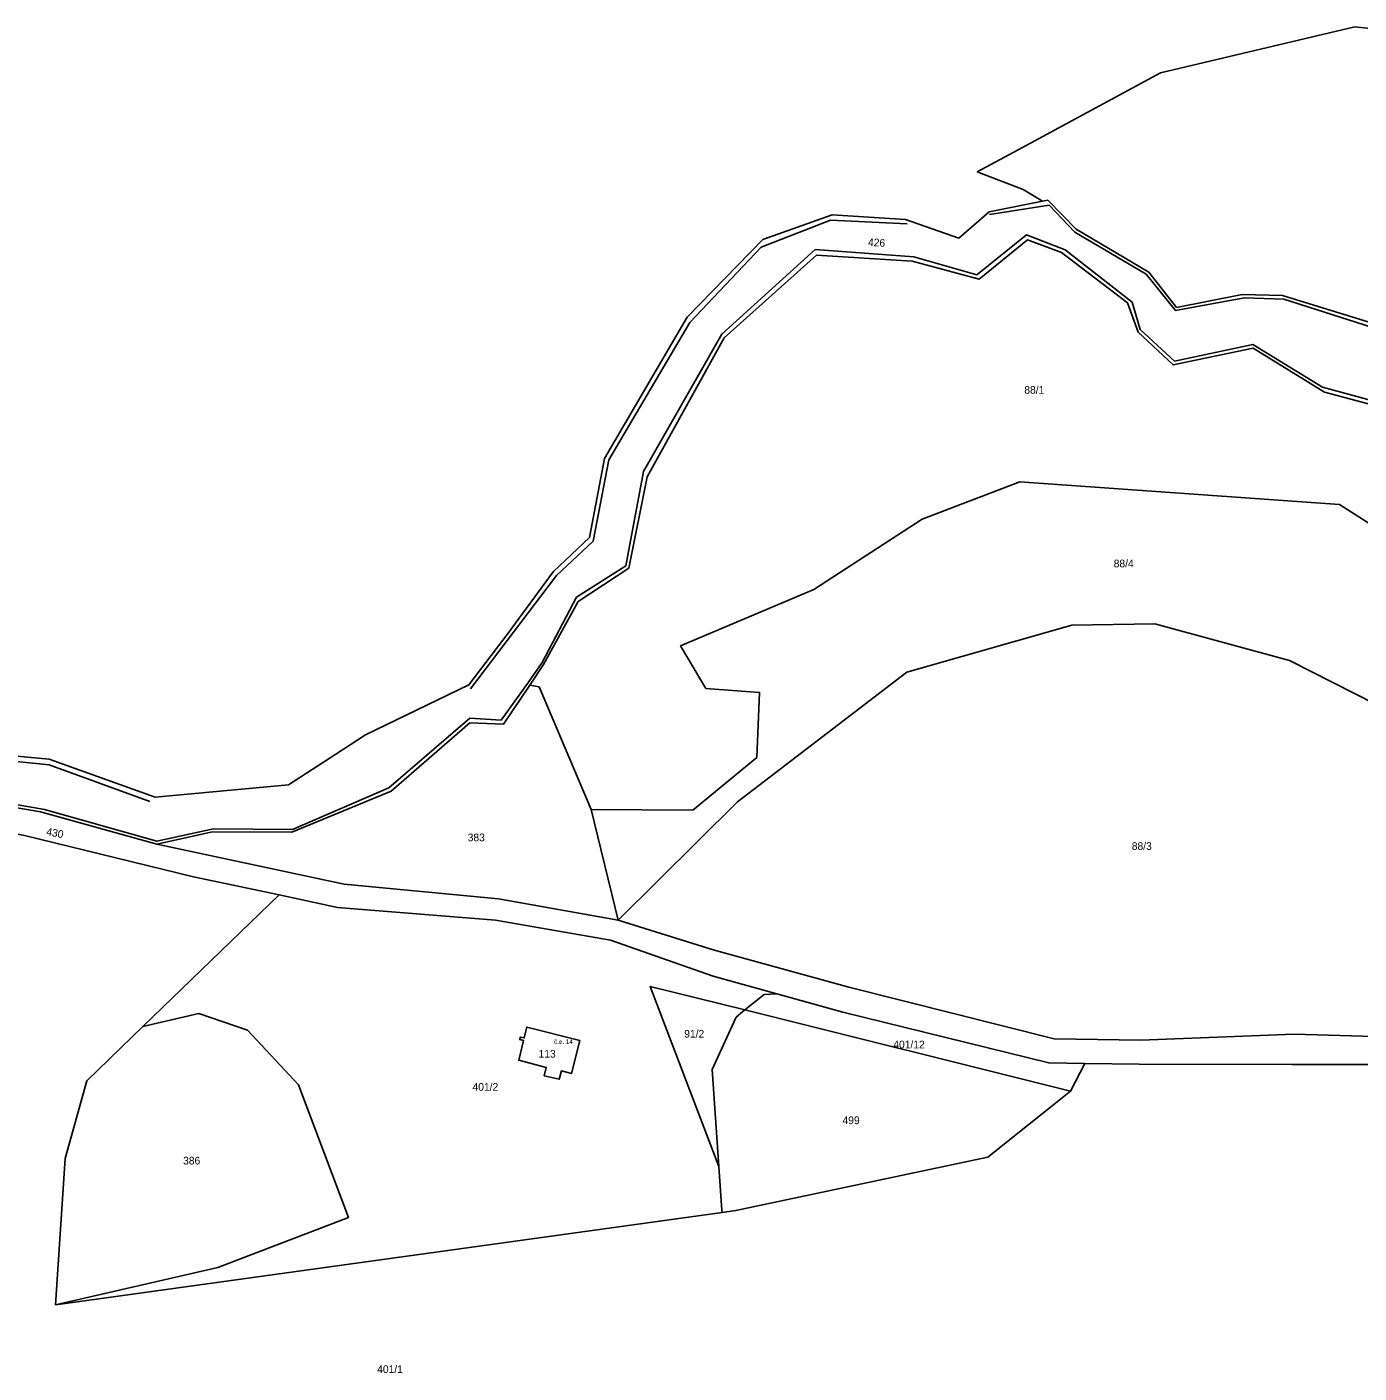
# Model space of a CAD drawing. Extents: x -887272 to -877616, y -1026687 to -1019819.
# Drawn here: x -879371.3 to -879076.4, y -1022593 to -1022295 of the extents above; entities that cross this region are included whole.
import ezdxf

# ---------------------------------------------------------------- set-up
doc = ezdxf.new("R2010")
doc.units = 0
for name, color, linetype in [('Definiční body', 7, 'Continuous'), ('Hranice parcel', 7, 'Continuous'), ('Parcelní čísla', 7, 'Continuous'), ('Polygon budovy', 7, 'Continuous'), ('Vnitřní kresba', 7, 'Continuous')]:
    doc.layers.add(name, color=color, linetype=linetype)

msp = doc.modelspace()

# ---------------------------------------------------------------- linework, layer by layer
at = {"layer": 'Hranice parcel'}
for p, q in [((-879151.81, -1022322.15), (-879160.92, -1022327.07)), ((-879160.92, -1022327.07), (-879150.75, -1022330.99)), ((-879150.75, -1022330.99), (-879146.4, -1022333.58)), ((-879158.22, -1022335.9), (-879164.92, -1022341.71)), ((-879146.4, -1022333.58), (-879158.22, -1022335.9)), ((-879176.78, -1022337.61), (-879193.03, -1022336.61)), ((-879164.92, -1022341.71), (-879176.78, -1022337.61)), ((-879254.77, -1022415.62), (-879264.75, -1022429.21)), ((-879259.95, -1022440.7), (-879265.79, -1022449.37)), ((-879296.28, -1022451.71), (-879302.87, -1022455.98)), ((-879246.33, -1022468.23), (-879240.35, -1022492.73)), ((-879345.58, -1022516.31), (-879315.42, -1022487.17)), ((-879214.28, -1022514.25), (-879212.3, -1022512.64)), ((-879212.3, -1022512.64), (-879140.2, -1022530.61)), ((-879137.04, -1022524.47), (-879140.2, -1022530.61)), ((-879217.39, -1022556.97), (-879218.05, -1022547.29)), ((-879217.35, -1022557.49), (-879364.9, -1022577.89)), ((-879217.35, -1022557.49), (-879217.39, -1022556.97))]:
    msp.add_line(p, q, dxfattribs=at)
for points in [[(-878982.43, -1022318.67), (-879021.4, -1022300.98), (-879077.31, -1022294.97), (-879120.32, -1022305.15), (-879151.81, -1022322.15)], [(-879146.4, -1022333.58), (-879145.24, -1022333.35), (-879138.95, -1022339.75), (-879122.89, -1022349.24), (-879116.77, -1022357.07), (-879102.22, -1022354.24), (-879093.28, -1022354.46), (-879071.03, -1022361.28), (-879058.07, -1022372.29), (-879026.73, -1022401.71), (-878991.96, -1022434.26), (-878975.52, -1022443.78), (-878906.92, -1022482.11)], [(-879193.03, -1022336.61), (-879208.36, -1022342.07), (-879225.07, -1022359.23), (-879243.4, -1022390.51), (-879246.72, -1022408.02), (-879254.77, -1022415.62)], [(-879099.81, -1022366.11), (-879117.54, -1022369.81), (-879125.28, -1022362.52), (-879127.61, -1022356.05), (-879142.22, -1022344.89), (-879149.78, -1022342.12), (-879160.43, -1022350.81), (-879175.32, -1022346.83), (-879196.44, -1022345.53), (-879216.89, -1022363.83), (-879233.92, -1022394.6), (-879238.02, -1022414.84), (-879249.26, -1022422.2), (-879256.89, -1022436.17), (-879259.95, -1022440.7)], [(-879064.88, -1022380.92), (-879084.02, -1022375.86), (-879099.81, -1022366.11)], [(-879246.33, -1022468.23), (-879223.81, -1022468.41), (-879209.64, -1022456.73), (-879209.06, -1022442.32), (-879220.96, -1022441.45), (-879226.56, -1022432.02), (-879197.08, -1022419.54), (-879173.11, -1022403.96), (-879151.46, -1022395.72), (-879080.65, -1022400.74), (-879047.37, -1022421.96), (-879025.33, -1022451.91), (-879027.21, -1022459.61), (-878985.13, -1022493.99), (-878968.86, -1022531.3)], [(-878968.86, -1022531.3), (-878987.7, -1022508.24), (-879019.63, -1022480.84), (-879053.22, -1022454.85), (-879091.78, -1022435.29), (-879121.6, -1022427.16), (-879139.91, -1022427.41), (-879176.5, -1022437.82), (-879213.92, -1022466.57), (-879240.35, -1022492.73)], [(-879264.75, -1022429.21), (-879273.42, -1022440.64), (-879296.28, -1022451.71)], [(-879259.95, -1022440.7), (-879257.88, -1022441.09), (-879246.33, -1022468.23)], [(-879302.87, -1022455.98), (-879313.33, -1022462.75), (-879342.88, -1022465.55), (-879366.37, -1022457.08), (-879391.08, -1022454.8), (-879438.6, -1022449.35), (-879461.44, -1022456.65), (-879477.14, -1022457.02)], [(-879265.79, -1022449.37), (-879273.18, -1022449.04), (-879290.63, -1022464.2), (-879312.6, -1022473.29), (-879330.15, -1022473.16), (-879342.53, -1022475.91)], [(-879435.67, -1022463.03), (-879388.26, -1022465.34), (-879368.23, -1022468.76), (-879342.53, -1022475.91)], [(-879315.42, -1022487.17), (-879334.41, -1022483.12), (-879372.08, -1022473.95), (-879393.87, -1022470.04), (-879435.61, -1022467.78)], [(-879342.53, -1022475.91), (-879301.02, -1022484.77), (-879266.84, -1022488.04), (-879240.35, -1022492.73)], [(-879205.21, -1022509.09), (-879219.34, -1022505.17), (-879242.06, -1022497.17), (-879267.55, -1022492.75), (-879302.54, -1022489.92), (-879315.42, -1022487.17)], [(-879240.35, -1022492.73), (-879219.37, -1022499.31), (-879189.31, -1022507.6), (-879143.86, -1022518.99), (-879124.64, -1022519.3), (-879090.74, -1022517.98), (-879029.81, -1022519.8), (-878968.86, -1022531.3)], [(-879212.3, -1022512.64), (-879233.27, -1022507.42), (-879218.05, -1022547.29)], [(-879212.3, -1022512.64), (-879208.03, -1022509.18), (-879205.21, -1022509.09)], [(-879205.21, -1022509.09), (-879190.61, -1022513.15), (-879145.04, -1022524.35), (-879137.04, -1022524.47)], [(-879364.9, -1022577.89), (-879329.01, -1022569.67), (-879300.09, -1022558.59), (-879311.13, -1022529.2), (-879322.46, -1022517.11), (-879333.2, -1022513.42), (-879345.58, -1022516.31)], [(-879218.05, -1022547.29), (-879219.54, -1022525.8), (-879214.28, -1022514.25)], [(-879345.58, -1022516.31), (-879358.01, -1022528.29), (-879362.82, -1022545.49), (-879364.9, -1022577.89)], [(-879250.67, -1022526.68), (-879252.94, -1022526.13), (-879253.4, -1022527.97), (-879256.73, -1022527.19), (-879256.3, -1022525.37), (-879262.38, -1022523.78), (-879261.31, -1022519.37), (-879262.17, -1022519.19), (-879262.06, -1022518.65), (-879261.18, -1022518.84), (-879260.6, -1022516.43), (-879248.88, -1022519.37), (-879250.67, -1022526.68)], [(-878950.5, -1022545.95), (-878971.2, -1022539.15), (-879029.87, -1022524.72), (-879091.18, -1022524.72), (-879125.05, -1022524.64), (-879137.04, -1022524.47)], [(-879140.2, -1022530.61), (-879158.56, -1022545.26), (-879214.32, -1022557.07), (-879217.35, -1022557.49)]]:
    msp.add_lwpolyline(points, dxfattribs=at)
at = {"layer": 'Polygon budovy'}
msp.add_lwpolyline([(-879262.38, -1022523.78), (-879256.3, -1022525.37), (-879256.73, -1022527.19), (-879253.4, -1022527.97), (-879252.94, -1022526.13), (-879250.67, -1022526.68), (-879248.88, -1022519.37), (-879260.6, -1022516.43), (-879261.18, -1022518.84), (-879262.06, -1022518.65), (-879262.17, -1022519.19), (-879261.31, -1022519.37)], close=True, dxfattribs=at)
at = {"layer": 'Vnitřní kresba'}
for p, q in [((-879193.4, -1022337.78), (-879208.72, -1022343.77)), ((-879176.43, -1022338.6), (-879193.4, -1022337.78)), ((-879208.72, -1022343.77), (-879224.51, -1022360.39)), ((-879224.51, -1022360.39), (-879242.46, -1022390.81)), ((-879242.46, -1022390.81), (-879245.91, -1022408.84)), ((-879245.91, -1022408.84), (-879254.03, -1022416.46)), ((-879254.03, -1022416.46), (-879273.04, -1022441.55)), ((-879366.33, -1022458.33), (-879401.32, -1022454.88)), ((-879344.03, -1022466.47), (-879366.33, -1022458.33)), ((-879312.43, -1022472.65), (-879291.15, -1022463.47))]:
    msp.add_line(p, q, dxfattribs=at)
for points in [[(-879027.78, -1022402.72), (-879058.96, -1022372.59), (-879071.52, -1022362.09), (-879092.98, -1022355.25), (-879101.73, -1022354.93), (-879116.99, -1022357.79), (-879123.51, -1022349.68), (-879139.25, -1022340.45), (-879144.98, -1022334.41), (-879158.17, -1022336.48)], [(-879160.96, -1022349.83), (-879149.97, -1022340.97), (-879141.38, -1022344.31), (-879126.59, -1022355.93), (-879124.84, -1022361.97), (-879117.21, -1022368.97), (-879099.88, -1022365.31), (-879084.46, -1022374.7), (-879064.11, -1022380.26), (-879031.83, -1022407.63), (-878998.37, -1022439.56), (-878906.15, -1022493.65), (-878902.18, -1022495.4), (-878889.14, -1022501.28), (-878867.5, -1022509.14)], [(-879291.15, -1022463.47), (-879273.18, -1022447.99), (-879266.28, -1022448.5), (-879260.22, -1022440.08), (-879257.19, -1022435.7), (-879249.62, -1022421.23), (-879238.69, -1022414.32), (-879234.74, -1022393.41), (-879217.41, -1022363.03), (-879196.74, -1022344.26), (-879174.95, -1022345.85), (-879160.96, -1022349.83)], [(-879435.37, -1022462.26), (-879387.96, -1022464.66), (-879367.35, -1022468.28)], [(-879367.35, -1022468.28), (-879342.47, -1022475.26), (-879329.93, -1022472.56), (-879312.43, -1022472.65)]]:
    msp.add_lwpolyline(points, dxfattribs=at)

# ---------------------------------------------------------------- texts
at = {"layer": 'Definiční body'}
msp.add_text('č.e. 14', height=1, dxfattribs=at).set_placement((-879254.57, -1022520.14))
at = {"layer": 'Parcelní čísla'}
for s, rotation, p in [('426', 357, (-879185.1, -1022343.46)), ('430', 349, (-879367.07, -1022473.9))]:
    msp.add_text(s, height=1.7, rotation=rotation, dxfattribs=at).set_placement(p)
for s, p in [('88/1', (-879150.46, -1022376.19)), ('88/4', (-879130.67, -1022414.63)), ('383', (-879273.68, -1022475.28)), ('88/3', (-879126.67, -1022477.19)), ('91/2', (-879225.74, -1022518.75)), ('401/12', (-879179.46, -1022521.13)), ('113', (-879257.99, -1022523.18)), ('401/2', (-879272.61, -1022530.52)), ('499', (-879190.7, -1022537.91)), ('386', (-879336.68, -1022546.85)), ('401/1', (-879293.72, -1022593.01))]:
    msp.add_text(s, height=1.7, dxfattribs=at).set_placement(p)

doc.saveas('drawing.dxf')
